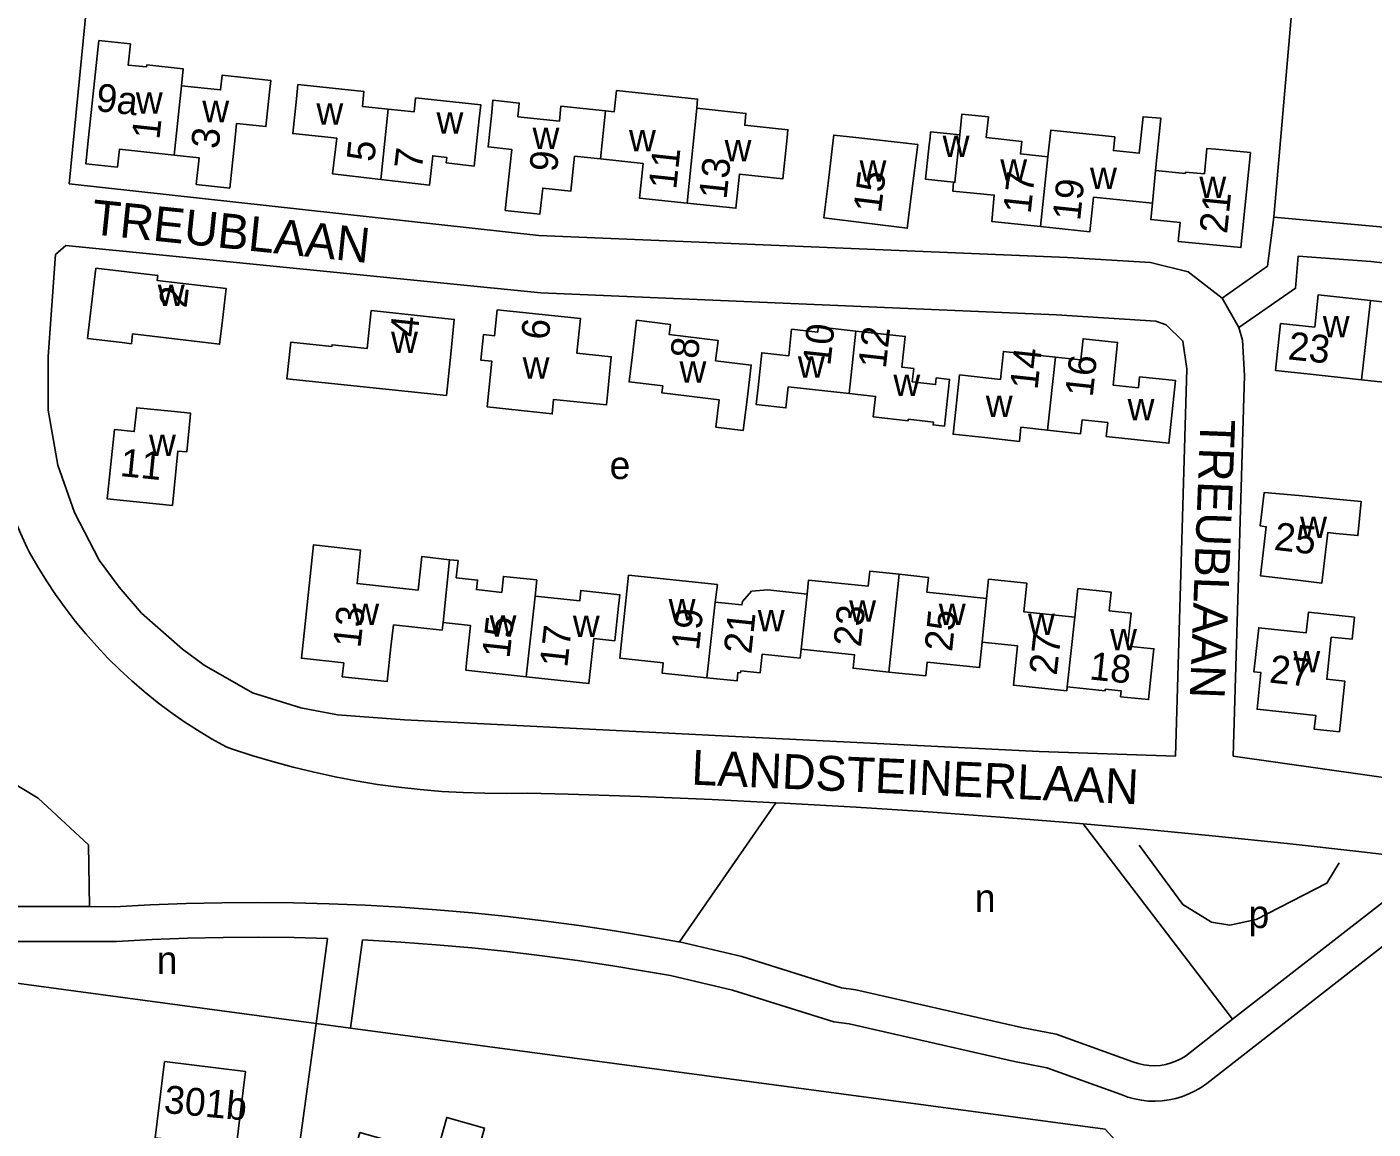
# Model space of a CAD drawing. Extents: x 161093 to 163177, y 379000 to 380904.
# Drawn here: x 162285.6 to 162479, y 380357.5 to 380515.9 of the extents above; entities that cross this region are included whole.
import ezdxf

# ---------------------------------------------------------------- set-up
doc = ezdxf.new("R2010")
doc.units = 0
for name, color, linetype in [('BLT_Basislijn', 7, 'Continuous'), ('BLT_Bebouwing', 7, 'Continuous'), ('BLT_Centroide', 7, 'Continuous'), ('BLT_Huisnummer', 7, 'Continuous'), ('BLT_Huisnummer_reeks', 7, 'Continuous'), ('BLT_Huisnummer_zonder_bebouwing', 7, 'Continuous'), ('BLT_Onderverdeling_panden', 7, 'Continuous'), ('BLT_Plantopo', 7, 'Continuous'), ('BLT_Straatnaam', 7, 'Continuous')]:
    doc.layers.add(name, color=color, linetype=linetype)

msp = doc.modelspace()

# ---------------------------------------------------------------- linework, layer by layer
at = {"layer": 'BLT_Basislijn'}
for p, q in [((162467.28, 380517.75), (162464.76, 380488.53)), ((162457.34, 380476.87), (162459.73, 380472.66)), ((162393.21, 380404.4), (162379.35, 380384.39)), ((162437.34, 380401.35), (162458.81, 380373.28)), ((162221.79, 380386.84), (162296.86, 380376.73)), ((162374.6, 380385.21), (162379.19, 380384.43)), ((162291.68, 380384.47), (162298.46, 380384.47)), ((162327.12, 380372.67), (162328.78, 380384.89)), ((162332.08, 380372.01), (162333.8, 380384.69)), ((162379.35, 380384.39), (162379.19, 380384.43)), ((162373.75, 380380.29), (162378.05, 380379.56)), ((162324.05, 380350.03), (162327.12, 380372.67)), ((162327.12, 380372.67), (162332.08, 380372.01)), ((162458.81, 380373.28), (162452.05, 380368))]:
    msp.add_line(p, q, dxfattribs=at)
for points in [[(162469.52, 380533.87), (162470.66, 380544.45), (162470.95, 380544.57), (162488.98, 380542.76), (162489.07, 380542.53), (162484.46, 380499.64), (162483.46, 380487.1), (162482.67, 380486.89), (162464.76, 380488.53)], [(162294.9, 380526.57), (162291.65, 380493.33), (162359.14, 380485.89), (162435.1, 380482.76), (162447.03, 380482.03), (162452.42, 380480.7), (162457.34, 380476.87)], [(162457.34, 380476.87), (162463.86, 380481.51), (162464.76, 380488.53)], [(162359.42, 380477.68), (162291.15, 380484.48), (162289.7, 380483.17), (162288.64, 380468.51), (162288.64, 380460.82), (162290.04, 380452.88), (162292.43, 380446.12), (162295.98, 380439.27), (162298.83, 380435.37), (162302.06, 380431.61), (162307.93, 380426.48), (162311.03, 380424.18), (162317.99, 380420.2), (162324.94, 380418.05), (162330.2, 380417.05), (162339.84, 380416.31), (162385.42, 380414.03)], [(162256.04, 380483.15), (162269.8, 380477.92), (162272.82, 380459.64), (162270.97, 380452.4), (162262.15, 380444.96), (162265.17, 380424.18), (162271.55, 380414.51), (162287.19, 380405.04), (162294.42, 380398.33), (162294.58, 380389.47)], [(162459.73, 380472.66), (162467.88, 380478.31), (162468.26, 380482.93), (162478.71, 380482.18), (162522.1, 380477.28), (162521.36, 380467.47)], [(162431.01, 380411.76), (162450.6, 380411.07), (162452.23, 380466.73), (162451.69, 380470.73), (162449.3, 380473.05), (162447.8, 380473.58), (162433.53, 380474.48), (162359.42, 380477.68)], [(162279.87, 380474.02), (162279.69, 380471.77), (162279.6, 380469.51), (162279.59, 380467.26), (162279.65, 380465), (162279.8, 380462.75), (162280.03, 380460.5), (162280.34, 380458.27), (162280.72, 380456.04), (162281.18, 380453.83), (162281.73, 380451.64), (162282.35, 380449.47), (162283.04, 380447.33), (162283.81, 380445.21), (162284.66, 380443.11), (162285.59, 380441.04)], [(162458.92, 380411.1), (162460.54, 380465.78), (162460.26, 380470.86), (162459.73, 380472.66)], [(162521.36, 380467.47), (162518.79, 380461.74), (162516, 380403), (162458.92, 380411.1)], [(162314.19, 380412.42), (162312.12, 380413.58), (162310.1, 380414.8), (162308.11, 380416.09), (162306.17, 380417.45), (162304.28, 380418.87), (162302.44, 380420.36), (162300.65, 380421.91), (162298.91, 380423.51), (162297.22, 380425.18), (162295.6, 380426.9), (162294.03, 380428.67), (162292.52, 380430.5), (162291.08, 380432.38), (162289.7, 380434.3), (162288.39, 380436.27), (162287.14, 380438.28), (162285.96, 380440.34), (162285.59, 380441.04)], [(162385.42, 380414.03), (162431.01, 380411.76)], [(162357.54, 380405.79), (162354.45, 380405.73), (162351.36, 380405.75), (162348.27, 380405.85), (162345.18, 380406.03), (162342.1, 380406.29), (162339.02, 380406.62), (162335.96, 380407.04), (162332.91, 380407.54), (162329.87, 380408.11), (162326.85, 380408.77), (162323.84, 380409.5), (162320.86, 380410.31), (162317.9, 380411.19), (162314.96, 380412.16), (162314.19, 380412.42)], [(162393.21, 380404.4), (162384.05, 380404.85), (162373.7, 380405.28), (162363.34, 380405.63), (162357.54, 380405.79)], [(162437.34, 380401.35), (162435.75, 380401.49), (162425.42, 380402.32), (162415.08, 380403.08), (162404.74, 380403.75), (162394.4, 380404.34), (162393.21, 380404.4)], [(162486.27, 380396.27), (162476.99, 380397.38), (162466.69, 380398.52), (162456.38, 380399.59), (162446.07, 380400.58), (162437.34, 380401.35)], [(162445.38, 380398.32), (162451.67, 380389.77), (162455.82, 380387.24), (162458.45, 380386.81), (162462.22, 380387.61), (162472.39, 380392.83), (162474.16, 380395.74)], [(162492.4, 380395.48), (162483.87, 380386.47), (162455.12, 380364.06)], [(162486.27, 380396.27), (162480.5, 380390.18), (162458.81, 380373.28)], [(162222.23, 380392.3), (162250.71, 380387.5), (162271.57, 380385.38), (162281.63, 380384.47), (162291.68, 380384.47)], [(162255.08, 380392.08), (162272.05, 380390.36), (162281.86, 380389.47), (162294.58, 380389.47)], [(162294.58, 380389.47), (162298.15, 380389.46), (162303.3, 380389.73), (162308.44, 380389.92), (162313.59, 380390.03), (162318.74, 380390.06), (162323.88, 380390.01), (162329.03, 380389.88), (162334.17, 380389.67), (162339.31, 380389.39), (162344.45, 380389.02), (162349.57, 380388.57), (162354.7, 380388.04), (162359.81, 380387.43), (162364.91, 380386.74), (162370, 380385.98), (162374.6, 380385.21)], [(162298.46, 380384.47), (162303.56, 380384.74), (162308.66, 380384.93), (162313.77, 380385.04), (162318.88, 380385.06), (162323.99, 380385.01), (162328.78, 380384.89)], [(162333.8, 380384.69), (162339.3, 380384.38), (162344.4, 380384), (162349.49, 380383.55), (162354.57, 380383.02), (162359.64, 380382.41), (162364.7, 380381.72), (162369.75, 380380.95), (162373.75, 380380.29)], [(162444.5, 380367.18), (162433.47, 380371.16), (162428.5, 380372.09), (162404.67, 380377.53), (162402.65, 380377.82), (162388.31, 380382.3), (162379.35, 380384.39)], [(162442.8, 380362.48), (162432.15, 380366.32), (162427.49, 380367.2), (162403.75, 380372.61), (162401.55, 380372.92), (162386.99, 380377.47), (162378.05, 380379.56)], [(162327.12, 380372.67), (162296.86, 380376.73)], [(162444.84, 380352.76), (162440.5, 380357.48), (162332.08, 380372.01)], [(162444.5, 380367.18), (162445.26, 380366.92), (162446.05, 380366.74), (162446.85, 380366.63), (162447.65, 380366.61), (162448.45, 380366.66), (162449.25, 380366.8), (162450.02, 380367.01), (162450.78, 380367.3), (162451.5, 380367.66), (162452.05, 380368)], [(162455.12, 380364.06), (162454.31, 380363.49), (162453.45, 380362.98), (162452.55, 380362.55), (162451.62, 380362.19), (162450.67, 380361.9), (162449.7, 380361.69), (162448.71, 380361.56), (162447.71, 380361.51), (162446.72, 380361.54), (162445.73, 380361.65), (162444.75, 380361.84), (162443.79, 380362.11), (162442.8, 380362.48)]]:
    msp.add_lwpolyline(points, dxfattribs=at)
at = {"layer": 'BLT_Bebouwing'}
for points in [[(162307.77, 380507.41), (162308.02, 380509.86), (162302.79, 380510.41), (162302.76, 380510.11), (162300.12, 380510.39), (162300.44, 380513.42), (162295.92, 380513.9), (162294.45, 380500), (162294.05, 380496.21), (162298.57, 380495.72), (162298.86, 380498.3), (162306.72, 380497.44)], [(162307.77, 380507.41), (162313.4, 380506.82), (162313.62, 380508.93), (162320.61, 380508.19), (162320.44, 380506.51), (162319.91, 380501.54), (162315.69, 380501.98), (162315.48, 380500), (162314.72, 380492.72), (162309.92, 380493.24), (162310.34, 380497.05), (162306.72, 380497.44)], [(162336.43, 380493.93), (162329.49, 380494.74), (162330.09, 380499.87), (162328.81, 380500.02), (162323.78, 380500.55), (162324.3, 380505.52), (162324.52, 380507.57), (162334.01, 380506.57), (162333.79, 380504.44), (162337.5, 380504.05)], [(162337.5, 380504.05), (162341.21, 380503.66), (162341.42, 380505.67), (162350.79, 380504.68), (162350.58, 380502.68), (162350.29, 380500), (162349.86, 380495.87), (162345.81, 380496.34), (162345.9, 380497.11), (162343.9, 380497.35), (162343.41, 380493.12), (162336.43, 380493.93)], [(162368.73, 380503.79), (162362.31, 380504.47), (162362.09, 380502.34), (162356.12, 380502.97), (162356.33, 380504.92), (162352.55, 380505.32), (162352.37, 380503.59), (162351.99, 380500), (162351.85, 380498.62), (162355.24, 380498.26), (162354.32, 380489.51), (162359.29, 380488.98), (162359.69, 380492.71), (162363.75, 380492.28), (162364.28, 380497.29), (162368, 380496.9)], [(162381.82, 380504.17), (162381.96, 380505.49), (162370.28, 380506.72), (162369.96, 380503.66), (162368.73, 380503.79)], [(162380.47, 380490.54), (162387.46, 380489.81), (162387.97, 380494.71), (162394.2, 380494.05), (162394.72, 380499.03), (162394.82, 380500), (162394.93, 380501.08), (162388.73, 380501.73), (162388.9, 380503.43), (162381.82, 380504.17)], [(162432.3, 380497.2), (162428.35, 380497.61), (162428.54, 380499.42), (162423.43, 380499.96), (162423.74, 380502.93), (162419.91, 380503.32), (162419.61, 380500.36)], [(162432.3, 380497.2), (162432.72, 380501.04), (162441.9, 380500.05), (162441.7, 380498.11), (162445.41, 380497.71), (162445.97, 380502.96), (162448.52, 380502.74), (162447.77, 380495.25)], [(162412.69, 380491.9), (162413.58, 380498.95), (162404.71, 380500), (162401.52, 380500.33), (162401.49, 380500), (162400.7, 380493.4), (162400.1, 380488.43), (162412.07, 380486.94), (162412.69, 380491.9)], [(162419.61, 380500.36), (162415.44, 380500.79), (162415.36, 380500), (162415.24, 380498.94), (162414.71, 380493.97), (162418.74, 380493.57)], [(162456.41, 380498.29), (162461.38, 380497.8), (162460.03, 380484.16), (162451.01, 380485.05), (162451.28, 380487.78), (162447.07, 380488.19), (162447.3, 380490.52)], [(162447.77, 380495.25), (162452.05, 380494.82), (162452.07, 380495.02), (162454.77, 380494.76), (162455.13, 380498.42), (162456.41, 380498.29)], [(162380.47, 380490.54), (162373.59, 380491.27), (162374.11, 380496.25), (162368, 380496.9)], [(162418.74, 380493.57), (162418.62, 380492.28), (162424.58, 380491.71), (162424.21, 380487.93), (162431.24, 380487.18)], [(162447.3, 380490.52), (162438.85, 380491.42), (162438.32, 380486.43), (162431.24, 380487.18)], [(162313.62, 380473.31), (162314.21, 380478.28), (162304.29, 380479.45), (162304.37, 380480.15), (162295.5, 380481.2), (162294.3, 380471.1), (162299.27, 380470.51), (162300.59, 380470.35), (162300.76, 380471.76), (162313.26, 380470.28), (162313.62, 380473.31)], [(162465.73, 380473.27), (162470.63, 380472.75), (162471.12, 380477.36), (162478.63, 380476.57)], [(162478.63, 380476.57), (162481.72, 380476.24), (162481.88, 380477.77), (162491.23, 380476.79), (162490.93, 380474.06)], [(162346.47, 380468.87), (162345.85, 380462.91), (162322.92, 380465.32), (162323.48, 380470.57), (162329.41, 380469.95), (162329.44, 380470.2), (162334.47, 380469.67), (162335.05, 380475.1), (162346.99, 380473.85), (162346.47, 380468.87)], [(162369.04, 380463.49), (162369.55, 380468.47), (162364.6, 380468.97), (162365.11, 380473.98), (162353.17, 380475.2), (162352.79, 380471.5), (162351.2, 380471.67), (162350.81, 380467.98), (162352.4, 380467.84), (162351.72, 380461.27), (162361.06, 380460.26), (162361.24, 380462.32), (162368.84, 380461.55), (162369.04, 380463.49)], [(162389.05, 380462.32), (162389.65, 380467.28), (162384.53, 380467.9), (162384.89, 380470.81), (162377.88, 380471.66), (162378.05, 380473.13), (162373.18, 380473.72), (162372.58, 380468.76), (162372.11, 380464.86), (162376.95, 380464.28), (162376.83, 380463.29), (162385.05, 380462.29), (162384.57, 380458.36), (162388.51, 380457.88), (162389.05, 380462.32)], [(162403.73, 380463.18), (162394.97, 380464.13), (162394.64, 380461.13), (162390.37, 380461.6), (162390.64, 380464.07), (162391.18, 380469.04), (162395.04, 380468.61), (162395.46, 380472.42), (162399.22, 380472.01), (162399.3, 380472.77), (162404.71, 380472.17)], [(162404.71, 380472.17), (162411.8, 380471.39), (162411.31, 380466.96), (162413.02, 380466.77), (162412.79, 380464.88), (162416.15, 380464.48), (162416.25, 380465.43), (162418.16, 380465.22), (162417.42, 380458.49), (162415.79, 380458.68), (162415.84, 380459.1), (162412.22, 380459.5), (162412.2, 380459.28), (162407.19, 380459.83), (162407.52, 380462.77), (162403.73, 380463.18)], [(162477.37, 380465.18), (162469.98, 380465.96), (162465.01, 380466.49), (162465.73, 380473.27)], [(162432.25, 380457.92), (162436.99, 380457.42), (162437.2, 380459.4), (162440.88, 380459.01), (162440.67, 380457.02), (162449.67, 380456.05), (162450.64, 380465.04), (162445.47, 380465.6), (162445.3, 380464.01), (162441.65, 380464.4), (162442.31, 380470.54), (162437.35, 380471.07), (162437.02, 380468.04), (162433.38, 380468.43)], [(162432.25, 380457.92), (162428.41, 380458.34), (162428.19, 380456.31), (162423.22, 380456.85), (162418.67, 380457.34), (162419.06, 380460.89), (162419.59, 380465.86), (162425.46, 380465.23), (162425.89, 380469.24), (162433.38, 380468.43)], [(162490, 380467.14), (162485.25, 380467.64), (162485.04, 380465.63), (162480.65, 380466.1), (162480.52, 380464.84), (162477.37, 380465.18)], [(162309.04, 380459.77), (162308.54, 380454.8), (162307.28, 380454.93), (162306.49, 380447.12), (162297.13, 380448.06), (162298.14, 380458.02), (162301.01, 380457.73), (162301.35, 380461.14), (162306.3, 380460.64), (162309.1, 380460.36), (162309.04, 380459.77)], [(162468.35, 380448.52), (162463.37, 380448.98), (162462.81, 380444.16), (162463.66, 380444.06), (162462.84, 380436.99), (162467.8, 380436.41), (162471.66, 380435.96), (162472.5, 380443.21), (162473.67, 380443.07), (162476.84, 380442.78), (162477.29, 380447.69), (162474.24, 380447.97), (162468.35, 380448.52)], [(162337.88, 380426.79), (162337.35, 380421.82), (162330.89, 380422.51), (162331.11, 380424.49), (162325.01, 380425.15), (162325.54, 380430.12), (162326.75, 380441.43), (162333.53, 380440.7), (162333.01, 380435.88), (162341.78, 380434.94)], [(162341.78, 380434.94), (162342.31, 380439.76), (162346.29, 380439.32)], [(162346.29, 380439.32), (162347.53, 380439.18), (162347.26, 380436.72), (162350.33, 380436.38), (162350.18, 380435.02), (162353.82, 380434.62), (162354.06, 380436.91), (162358.83, 380436.41), (162358.6, 380434.1)], [(162397.68, 380434.38), (162397.9, 380436.39), (162406.46, 380435.49), (162406.69, 380437.66), (162410.9, 380437.22)], [(162410.9, 380437.22), (162415.11, 380436.78), (162414.89, 380434.66), (162423.48, 380433.76)], [(162383.29, 380422.34), (162376.86, 380423), (162377.01, 380424.49), (162376.12, 380424.59), (162370.79, 380425.15), (162371.04, 380427.51), (162371.56, 380432.48), (162372.04, 380437.08), (162384.79, 380435.74), (162384.49, 380433.22)], [(162423.48, 380433.76), (162423.77, 380436.5), (162429.27, 380435.93), (162428.84, 380431.81), (162436.18, 380431.04)], [(162357.32, 380422.5), (162366.34, 380421.51), (162367.06, 380427.99), (162370.04, 380427.67), (162370.58, 380432.64), (162370.77, 380434.28), (162365.17, 380434.9), (162365.01, 380433.39), (162358.6, 380434.1)], [(162384.49, 380433.22), (162388.33, 380432.81), (162388.38, 380433.31), (162389.72, 380434.8), (162392.02, 380434.97), (162397.68, 380434.38)], [(162436.18, 380431.04), (162436.61, 380435.17), (162441.37, 380434.67), (162441.09, 380431.97), (162444.25, 380431.64), (162443.75, 380426.91), (162447.52, 380426.53), (162447.39, 380425.22), (162446.75, 380419.21), (162442.73, 380419.63), (162442.82, 380420.47), (162440.54, 380420.71), (162440.51, 380420.46), (162435.06, 380421.03)], [(162472.99, 380428.2), (162472.35, 380422.15), (162474.94, 380421.87), (162474.18, 380414.59), (162470.53, 380414.98), (162470.81, 380416.91), (162462.34, 380417.82), (162462.9, 380423.09), (162461.9, 380423.2), (162462.08, 380424.84), (162462.58, 380429.54), (162469.41, 380428.81), (162469.72, 380431.76), (162476.33, 380431.05), (162475.99, 380427.88), (162472.99, 380428.2)], [(162338.23, 380429.98), (162337.88, 380426.79)], [(162345.37, 380430.27), (162345.25, 380429.2), (162338.23, 380429.98)], [(162357.32, 380422.5), (162348.64, 380423.46), (162348.81, 380424.96), (162349.34, 380429.84), (162345.37, 380430.27)], [(162396.85, 380426.47), (162396.69, 380425.17), (162391.21, 380425.74), (162390.93, 380423.04), (162388.14, 380423.33), (162388.11, 380423.07), (162387.75, 380423.11), (162387.62, 380421.9), (162383.29, 380422.34)], [(162409.42, 380423.18), (162404.3, 380423.72), (162404.51, 380425.66), (162396.85, 380426.47)], [(162422.86, 380427.47), (162422.47, 380423.82), (162414.94, 380424.61), (162414.73, 380422.62), (162409.42, 380423.18)], [(162435.06, 380421.03), (162435, 380420.49), (162427.34, 380421.29), (162427.93, 380426.94), (162422.86, 380427.47)]]:
    msp.add_lwpolyline(points, dxfattribs=at)
msp.add_lwpolyline([(162333.42, 380357), (162344.43, 380353.89), (162345.9, 380359.18), (162351.34, 380357.65), (162348.65, 380348.06), (162343.84, 380349.44), (162342.98, 380346.35), (162336.08, 380348.3), (162335.76, 380347.14), (162331.02, 380348.47)], close=True, dxfattribs=at)
at = {"layer": 'BLT_Onderverdeling_panden'}
for p, q in [((162307.77, 380507.41), (162306.72, 380497.44)), ((162337.5, 380504.05), (162336.43, 380493.93)), ((162368, 380496.9), (162368.73, 380503.79)), ((162381.82, 380504.17), (162380.47, 380490.54)), ((162432.3, 380497.2), (162431.24, 380487.18)), ((162447.77, 380495.25), (162447.3, 380490.52)), ((162478.63, 380476.57), (162477.37, 380465.18)), ((162403.73, 380463.18), (162404.71, 380472.17)), ((162433.38, 380468.43), (162432.25, 380457.92)), ((162346.29, 380439.32), (162345.37, 380430.27)), ((162410.9, 380437.22), (162409.42, 380423.18)), ((162358.6, 380434.1), (162357.32, 380422.5)), ((162397.68, 380434.38), (162396.85, 380426.47)), ((162423.48, 380433.76), (162422.86, 380427.47)), ((162384.49, 380433.22), (162383.29, 380422.34)), ((162436.18, 380431.04), (162435.06, 380421.03))]:
    msp.add_line(p, q, dxfattribs=at)
msp.add_lwpolyline([(162419.61, 380500.36), (162418.92, 380493.56), (162418.74, 380493.57)], dxfattribs=at)
at = {"layer": 'BLT_Plantopo'}
msp.add_lwpolyline([(162305.34, 380367.21), (162304, 380356.27), (162315.64, 380354.85), (162316.98, 380365.79)], close=True, dxfattribs=at)

# ---------------------------------------------------------------- texts
at = {"layer": 'BLT_Centroide'}
for s, p in [('w', (162301.23, 380503.4)), ('w', (162310.78, 380502.18)), ('w', (162327.17, 380501.82)), ('w', (162344.43, 380500.53)), ('w', (162358.23, 380498.33)), ('w', (162372.09, 380498)), ('w', (162385.83, 380496.57)), ('w', (162417.16, 380497.17)), ('w', (162405.22, 380493.62)), ('w', (162425.44, 380493.78)), ('w', (162438.34, 380492.56)), ('w', (162454.05, 380491.28)), ('w', (162304.38, 380475.75)), ('w', (162471.78, 380471.28)), ('w', (162337.9, 380469)), ('w', (162356.81, 380465.34)), ('w', (162396.36, 380465.45)), ('w', (162379.35, 380464.75)), ('w', (162410.08, 380462.84)), ('w', (162423.36, 380459.82)), ('w', (162443.74, 380459.35)), ('w', (162303.12, 380454.22)), ('e', (162369.31, 380450.9)), ('w', (162468.53, 380442.41)), ('w', (162377.79, 380430.59)), ('w', (162403.73, 380430.41)), ('w', (162332.33, 380429.93)), ('w', (162390.59, 380429)), ('w', (162416.61, 380429.91)), ('w', (162429.42, 380428.5)), ('w', (162352.06, 380428.27)), ('w', (162364.02, 380428.22)), ('w', (162441.22, 380426.3)), ('w', (162467.55, 380423.12)), ('n', (162421.79, 380388.72)), ('p', (162461.12, 380386.4)), ('n', (162304.23, 380379.8))]:
    msp.add_text(s, height=4, dxfattribs=at).set_placement(p)
at = {"layer": 'BLT_Huisnummer'}
for s, rotation, p in [('3', 84.0426, (162313.12, 380498.24)), ('5', 83.9857, (162335.48, 380496.4)), ('7', 83.365, (162342.32, 380495.27)), ('9', 83.981, (162361.73, 380494.92)), ('11', 83.9782, (162378.87, 380492.42)), ('13', 83.9807, (162386.1, 380491)), ('15', 82.8665, (162408.28, 380489.03)), ('17', 83.9275, (162429.81, 380488.92)), ('19', 83.9222, (162436.91, 380487.92)), ('21', 84.3289, (162458.03, 380486.06)), ('2', 83.2687, (162308.51, 380475.39)), ('4', 83.9952, (162341.7, 380471.19)), ('6', 84.1693, (162360.55, 380470.79)), ('10', 83.8136, (162401.02, 380467.09)), ('12', 83.718, (162408.99, 380466.68)), ('23', 353.9508, (162466.68, 380468.12)), ('8', 83.0811, (162381.97, 380468.06)), ('14', 83.8639, (162430.79, 380463.64)), ('16', 83.8621, (162438.72, 380462.6)), ('11', 354.2264, (162298.85, 380451.35)), ('25', 353.3283, (162464.67, 380440.75)), ('13', 83.8795, (162333.5, 380426.54)), ('19', 84.0078, (162382.15, 380426.18)), ('21', 84.0034, (162389.67, 380425.67)), ('23', 83.9999, (162405.42, 380426.68)), ('25', 84.33, (162418.52, 380426.01)), ('15', 83.7079, (162354.92, 380425.05)), ('17', 83.7151, (162363.22, 380423.73)), ('27', 83.6127, (162433.54, 380422.61)), ('18', 354.0159, (162438.14, 380422.13)), ('27', 353.9019, (162463.99, 380421.68))]:
    msp.add_text(s, height=4, rotation=rotation, dxfattribs=at).set_placement(p)
at = {"layer": 'BLT_Huisnummer_reeks'}
for s, rotation, p in [('9a', 353.7919, (162295.38, 380503.8)), ('1', 83.988, (162304.61, 380499.59))]:
    msp.add_text(s, height=4, rotation=rotation, dxfattribs=at).set_placement(p)
at = {"layer": 'BLT_Huisnummer_zonder_bebouwing'}
msp.add_text('301b', height=4, rotation=354.6645, dxfattribs=at).set_placement((162305.16, 380359.84))
at = {"layer": 'BLT_Straatnaam'}
for s, rotation, p in [('TREUBLAAN', 354.0497, (162294.69, 380486.1)), ('TREUBLAAN', 267.8181, (162454.21, 380459.56)), ('LANDSTEINERLAAN', 357.4626, (162381, 380407.01))]:
    msp.add_text(s, height=5, rotation=rotation, dxfattribs=at).set_placement(p)

doc.saveas('drawing.dxf')
